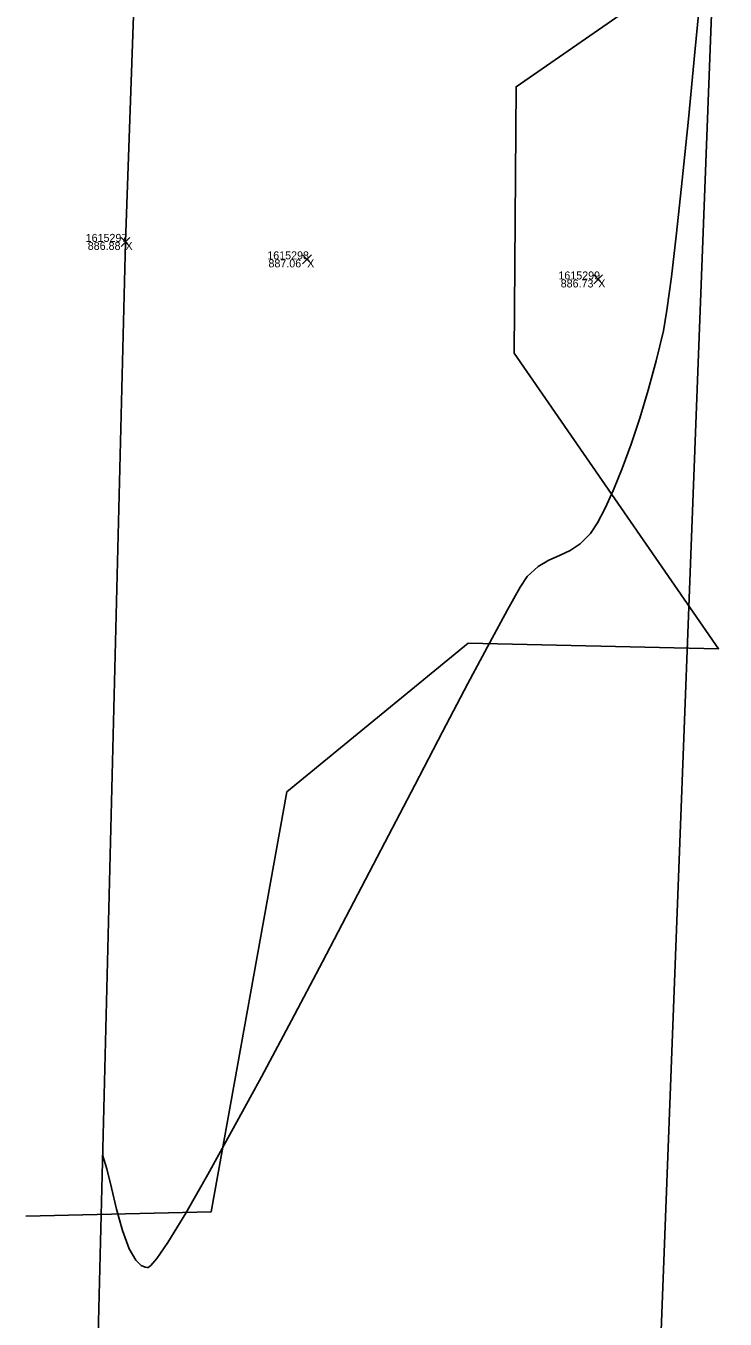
# Model space of a CAD drawing. Extents: x 1957117 to 1971063, y 701601 to 715861.
# Drawn here: x 1962670.2 to 1962700.8, y 702660.6 to 702717.2 of the extents above; entities that cross this region are included whole.
import ezdxf

# ---------------------------------------------------------------- set-up
doc = ezdxf.new("R2010")
doc.units = 0
for name, color, linetype in [('AP_X_Lights', 7, 'Continuous'), ('DT_X_Contour_Minor', 7, 'Continuous'), ('DT_X_TIN_Hull', 7, 'Continuous'), ('PV_P_Shoulder', 7, 'Continuous'), ('RS_Raster1', 7, 'Continuous'), ('RW_X_Esmt_RR', 7, 'Continuous'), ('SC_Scratch1', 7, 'Continuous'), ('VG_X_Tree_Line_Rt', 7, 'Continuous')]:
    doc.layers.add(name, color=color, linetype=linetype)

msp = doc.modelspace()

# ---------------------------------------------------------------- linework, layer by layer
at = {"layer": 'AP_X_Lights'}
for p, q in [((1962674.365, 702707.55), (1962674.753, 702707.94)), ((1962674.365, 702707.94), (1962674.753, 702707.55)), ((1962682.306, 702706.785), (1962682.694, 702707.175)), ((1962682.306, 702707.175), (1962682.694, 702706.785)), ((1962695.031, 702705.907), (1962695.419, 702706.297)), ((1962695.031, 702706.297), (1962695.419, 702705.907))]:
    msp.add_line(p, q, dxfattribs=at)
at = {"layer": 'DT_X_Contour_Minor'}
msp.add_lwpolyline([(1962699.752, 702719.192), (1962699.455, 702716.044), (1962699.169, 702713.108), (1962698.899, 702710.447), (1962698.649, 702708.127), (1962698.425, 702706.21), (1962698.231, 702704.763), (1962698.073, 702703.849), (1962697.759, 702702.539), (1962697.413, 702701.263), (1962697.045, 702700.041), (1962696.663, 702698.893), (1962696.277, 702697.841), (1962695.897, 702696.904), (1962695.531, 702696.104), (1962695.189, 702695.46), (1962694.881, 702694.992), (1962694.443, 702694.539), (1962693.995, 702694.245), (1962693.538, 702694.032), (1962693.073, 702693.824), (1962692.599, 702693.542), (1962692.117, 702693.108), (1962691.81, 702692.639), (1962691.254, 702691.656), (1962690.482, 702690.228), (1962689.528, 702688.426), (1962688.424, 702686.32), (1962687.203, 702683.98), (1962685.898, 702681.477), (1962684.542, 702678.881), (1962683.169, 702676.261), (1962681.811, 702673.688), (1962680.502, 702671.232), (1962679.274, 702668.963), (1962678.16, 702666.952), (1962677.194, 702665.268), (1962676.408, 702663.982), (1962675.932, 702663.286), (1962675.674, 702662.983), (1962675.554, 702662.893), (1962675.511, 702662.883), (1962675.419, 702662.898), (1962675.246, 702662.978), (1962675.007, 702663.213), (1962674.726, 702663.7), (1962674.425, 702664.51), (1962674.17, 702665.438), (1962673.948, 702666.373), (1962673.75, 702667.204), (1962673.563, 702667.819)], dxfattribs=at)
msp.add_lwpolyline([(1962699.752, 702719.192), (1962699.455, 702716.044), (1962699.169, 702713.108), (1962698.899, 702710.447), (1962698.649, 702708.127), (1962698.425, 702706.21), (1962698.231, 702704.763), (1962698.073, 702703.849), (1962697.759, 702702.539), (1962697.413, 702701.263), (1962697.045, 702700.041), (1962696.663, 702698.893), (1962696.277, 702697.841), (1962695.897, 702696.904), (1962695.531, 702696.104), (1962695.189, 702695.46), (1962694.881, 702694.992), (1962694.443, 702694.539), (1962693.995, 702694.245), (1962693.538, 702694.032), (1962693.073, 702693.824), (1962692.599, 702693.542), (1962692.117, 702693.108), (1962691.81, 702692.639), (1962691.254, 702691.656), (1962690.482, 702690.228), (1962689.528, 702688.426), (1962688.424, 702686.32), (1962687.203, 702683.98), (1962685.898, 702681.477), (1962684.542, 702678.881), (1962683.169, 702676.261), (1962681.811, 702673.688), (1962680.502, 702671.232), (1962679.274, 702668.963), (1962678.16, 702666.952), (1962677.194, 702665.268), (1962676.408, 702663.982), (1962675.932, 702663.286), (1962675.674, 702662.983), (1962675.554, 702662.893), (1962675.511, 702662.883), (1962675.419, 702662.898), (1962675.246, 702662.978), (1962675.007, 702663.213), (1962674.726, 702663.7), (1962674.425, 702664.51), (1962674.17, 702665.438), (1962673.948, 702666.373), (1962673.75, 702667.204), (1962673.563, 702667.819)], dxfattribs=at)
at = {"layer": 'DT_X_TIN_Hull'}
msp.add_lwpolyline([(1962718.773, 703557.311), (1962703.306, 703409.414), (1962697.925, 703356.404), (1962695.546, 703306.63), (1962694.034, 703257.479), (1962691.621, 703207.55), (1962688.754, 703157.586), (1962686.442, 703107.868), (1962686.061, 703058.162), (1962683.854, 703007.968), (1962682.867, 702957.165), (1962682.031, 702907.997), (1962680.969, 702857.205), (1962678.419, 702807.872), (1962676.351, 702757.317), (1962674.559, 702707.745), (1962673.32, 702658.081)], dxfattribs=at)
at = {"layer": 'RW_X_Esmt_RR'}
msp.add_lwpolyline([(1962674.265, 702039.003), (1962716.391, 703142.573)], dxfattribs=at)
at = {"layer": 'VG_X_Tree_Line_Rt'}
msp.add_lwpolyline([(1962696.216, 702782.334), (1962694.287, 702771.767), (1962699.02, 702766.634), (1962706.293, 702764.31), (1962715.616, 702768.106), (1962727.61, 702770.034), (1962727.178, 702765.403), (1962726.525, 702758.384), (1962725.131, 702753.245), (1962729.126, 702746.941), (1962734.679, 702742.064), (1962735.861, 702737.963), (1962729.516, 702739.254), (1962725.8, 702735.398), (1962722.722, 702725.435), (1962706.369, 702721.657), (1962696.946, 702718.198), (1962691.633, 702714.528), (1962691.558, 702702.871), (1962700.486, 702689.952), (1962689.534, 702690.193), (1962681.614, 702683.697), (1962678.307, 702665.324), (1962670.207, 702665.132)], dxfattribs=at)

# ---------------------------------------------------------------- texts
at = {"layer": 'PV_P_Shoulder'}
for s, p in [('886.88', (1962672.911, 702707.395)), ('887.06', (1962680.811, 702706.63)), ('886.73', (1962693.585, 702705.752))]:
    msp.add_text(s, height=0.35, dxfattribs=at).set_placement(p)
at = {"layer": 'RS_Raster1'}
for s, p in [('1615297', (1962672.82, 702707.745)), ('1615298', (1962680.759, 702706.98)), ('1615299', (1962693.484, 702706.102))]:
    msp.add_text(s, height=0.35, dxfattribs=at).set_placement(p)
at = {"layer": 'SC_Scratch1'}
for p in [(1962674.559, 702707.395), (1962682.5, 702706.63), (1962695.225, 702705.752)]:
    msp.add_text('X', height=0.35, dxfattribs=at).set_placement(p)

doc.saveas('drawing.dxf')
